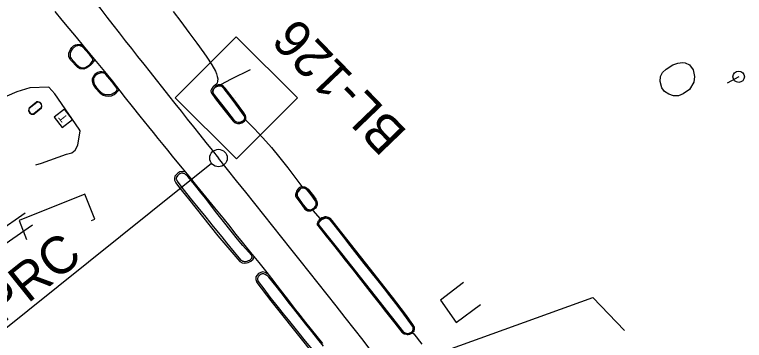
# Model space of a CAD drawing. Extents: x 471894 to 476235, y 503501 to 507878.
# Drawn here: x 473906 to 474218.9, y 505730.3 to 505870.1 of the extents above; entities that cross this region are included whole.
import ezdxf

# ---------------------------------------------------------------- set-up
doc = ezdxf.new("R2010")
doc.units = 0
for name, color, linetype in [('CTL Secondary Horizontal and Vertical CELL', 7, 'Continuous'), ('CTL Secondary Horizontal and Vertical Text', 7, 'Continuous'), ('Exist Horizontal Alignment', 7, 'Continuous'), ('Exist Other Culture Area Outline', 7, 'Continuous'), ('Exist Other Culture Sign', 7, 'Continuous'), ('Exist Roads Change in Surface', 7, 'Continuous'), ('Exist Roads Curbs', 7, 'Continuous'), ('Exist Roads EOP', 7, 'Continuous'), ('Exist Roads EOP Leader', 7, 'Continuous'), ('Exist Roads EOP Other', 7, 'Continuous'), ('Exist Roads Soil', 7, 'Continuous'), ('Exist Utilities Power Pole CELL', 7, 'Continuous'), ('Exist Utilities Telephone Pedestal CELL', 7, 'Continuous'), ('Exist Utilities Water Meter CELL', 7, 'Continuous')]:
    doc.layers.add(name, color=color, linetype=linetype)

msp = doc.modelspace()

# ---------------------------------------------------------------- linework, layer by layer
at = {"layer": 'CTL Secondary Horizontal and Vertical CELL'}
msp.add_line((474000.94, 505834.35), (474000.94, 505834.35), dxfattribs=at)
msp.add_lwpolyline([(473974.86, 505834.44), (474001.07, 505860.65), (474027.32, 505834.4), (474001.11, 505808.19)], close=True, dxfattribs=at)
at = {"layer": 'Exist Horizontal Alignment'}
msp.add_line((473990.5, 505806.21), (473896.83, 505731.16), dxfattribs=at)
msp.add_circle((473993.43, 505808.56), 3.75, dxfattribs=at)
for centre, radius, start, end in [((478558.54, 509466.62), 5849.93, 217.36226, 218.70549), ((466857.69, 500090.63), 9144.05, 37.455153, 38.70549)]:
    msp.add_arc(centre, radius, start, end, dxfattribs=at)
at = {"layer": 'Exist Other Culture Area Outline'}
msp.add_lwpolyline([(473938.96, 505781.69), (473940.43, 505782.28), (473936.12, 505793.05), (473907.96, 505781.79), (473911.21, 505773.67)], dxfattribs=at)
at = {"layer": 'Exist Other Culture Sign'}
for p, q in [((473910.56, 505784.93), (473869.89, 505756.79)), ((473873.24, 505752.05), (473913.74, 505779.89))]:
    msp.add_line(p, q, dxfattribs=at)
at = {"layer": 'Exist Roads Change in Surface'}
msp.add_lwpolyline([(474098.46, 505755.17), (474088.65, 505747.59), (474095.3, 505738.05), (474105.73, 505745.73)], dxfattribs=at)
at = {"layer": 'Exist Roads Curbs'}
for points in [[(473937.89, 505853.33), (473935.48, 505856.06), (473935.27, 505856.22), (473934.88, 505856.44), (473934.4, 505856.66), (473934.13, 505856.76), (473933.85, 505856.82), (473933.56, 505856.85), (473933.25, 505856.84), (473932.94, 505856.8), (473932.63, 505856.71), (473932.3, 505856.59), (473931.98, 505856.43), (473931.66, 505856.23), (473931.38, 505856.01), (473931.12, 505855.77), (473930.89, 505855.5), (473930.49, 505854.9), (473930.15, 505854.21), (473930.01, 505853.85), (473929.91, 505853.5), (473929.84, 505853.17), (473929.8, 505852.84), (473929.8, 505852.53), (473929.84, 505852.23), (473929.91, 505851.95), (473930.02, 505851.68), (473930.23, 505851.34), (473932.57, 505848.77), (473933.57, 505847.84), (473933.86, 505847.64), (473934.1, 505847.54), (473934.37, 505847.45), (473935.04, 505847.32), (473935.4, 505847.29), (473935.74, 505847.3), (473936.05, 505847.35), (473936.34, 505847.44), (473936.63, 505847.57), (473937.26, 505847.96), (473937.94, 505848.48), (473938.54, 505849.02), (473939.03, 505849.55), (473939.35, 505849.96), (473939.44, 505850.13), (473939.5, 505850.27), (473939.54, 505850.42), (473939.57, 505850.57), (473939.58, 505850.73), (473939.57, 505850.89), (473939.53, 505851.05), (473939.48, 505851.22), (473939.41, 505851.39), (473939.31, 505851.57), (473938.09, 505853.07)], [(473939.84, 505842.09), (473939.87, 505841.61), (473939.95, 505841.13), (473940.01, 505840.88), (473940.18, 505840.38), (473940.43, 505839.88), (473940.68, 505839.45), (473940.98, 505839.04), (473942.56, 505837.33), (473943.34, 505836.6), (473943.66, 505836.36), (473943.95, 505836.18), (473944.27, 505836.03), (473944.62, 505835.93), (473944.98, 505835.85), (473945.74, 505835.78), (473946.51, 505835.79), (473946.88, 505835.83), (473947.22, 505835.89), (473947.54, 505835.98), (473947.82, 505836.09), (473948.35, 505836.37), (473948.88, 505836.7), (473949.34, 505837.05), (473949.68, 505837.36), (473949.82, 505837.51), (473949.92, 505837.66), (473949.99, 505837.81), (473950.02, 505837.96), (473950.03, 505838.11), (473950.01, 505838.27), (473949.96, 505838.43), (473949.88, 505838.59), (473947.69, 505841.42), (473945.21, 505844.36), (473944.92, 505844.65), (473944.7, 505844.82), (473944.47, 505844.95), (473944.23, 505845.04), (473944, 505845.09), (473943.73, 505845.11), (473943.43, 505845.1), (473942.69, 505844.97), (473942.29, 505844.87), (473941.92, 505844.73), (473941.58, 505844.58), (473941.27, 505844.39), (473940.76, 505844.02), (473940.58, 505843.83), (473940.43, 505843.66), (473940.2, 505843.3), (473940, 505842.93), (473939.93, 505842.74), (473939.87, 505842.54), (473939.84, 505842.32)], [(473995.9, 505838.33), (473995.21, 505838.99), (473994.75, 505839.39), (473994.21, 505839.65), (473993.68, 505839.7), (473993.09, 505839.65), (473992.74, 505839.53), (473992.39, 505839.37), (473992.2, 505839.25), (473992.01, 505839.1), (473991.84, 505838.93), (473991.68, 505838.74), (473991.53, 505838.54), (473991.4, 505838.33), (473991.3, 505838.11), (473991.14, 505837.67), (473991.06, 505837.29), (473991.05, 505837.13), (473991.05, 505836.97), (473991.06, 505836.82), (473991.09, 505836.66), (473991.14, 505836.5), (473991.2, 505836.33), (473991.28, 505836.17), (473991.48, 505835.84), (473991.98, 505835.17), (473995.26, 505830.88), (473997.7, 505827.7), (473999.61, 505825.33), (474000.07, 505824.84), (474000.42, 505824.53), (474000.73, 505824.3), (474000.9, 505824.21), (474001.14, 505824.13), (474001.8, 505824), (474002.47, 505823.94), (474002.73, 505823.95), (474002.93, 505823.99), (474003.29, 505824.12), (474003.67, 505824.31), (474004.02, 505824.53), (474004.17, 505824.66), (474004.31, 505824.78), (474004.42, 505824.91), (474004.52, 505825.05), (474004.6, 505825.2), (474004.65, 505825.36), (474004.7, 505825.52), (474004.72, 505825.67), (474004.73, 505825.81), (474004.72, 505825.94), (474004.68, 505826.18), (474004.61, 505826.41), (474004.47, 505826.7), (474004.23, 505827.14), (474002.81, 505829.16), (474000.89, 505831.75), (473998.9, 505834.41)], [(473975.5, 505800.44), (473975.44, 505800.32), (473975.39, 505800.19), (473975.35, 505800.05), (473975.33, 505799.9), (473975.32, 505799.63), (473975.33, 505799.52), (473975.35, 505799.44), (473975.39, 505799.32), (473975.74, 505798.59), (473976, 505798.16), (473978.78, 505794.58), (473981.35, 505791.39), (473984.64, 505787.29), (473987.95, 505783.21), (473991.21, 505779.2), (473994.87, 505774.7), (473996.87, 505772.24), (474000.19, 505768.16), (474003.08, 505764.79), (474003.22, 505764.69), (474003.4, 505764.58), (474003.91, 505764.35), (474004.21, 505764.25), (474004.51, 505764.19), (474004.81, 505764.17), (474005.1, 505764.2), (474005.69, 505764.33), (474006.29, 505764.54), (474006.83, 505764.8), (474007.05, 505764.93), (474007.23, 505765.07), (474007.38, 505765.21), (474007.51, 505765.36), (474007.63, 505765.51), (474007.72, 505765.66), (474007.78, 505765.82), (474007.83, 505765.97), (474007.85, 505766.13), (474007.84, 505766.3), (474007.79, 505766.47), (474007.7, 505766.67), (474007.55, 505766.9), (474003.93, 505771.02), (474001.65, 505773.73), (473998.82, 505777.23), (473995.57, 505781.32), (473992.72, 505784.96), (473990.42, 505787.92), (473987.83, 505791.31), (473985.9, 505793.77), (473983.11, 505797.28), (473980.49, 505800.48), (473979.95, 505801.04), (473979.49, 505801.43), (473979.02, 505801.72), (473978.56, 505801.93), (473978.36, 505802), (473978.19, 505802.05), (473978.03, 505802.08), (473977.89, 505802.09), (473977.76, 505802.08), (473977.62, 505802.07), (473977.5, 505802.04), (473976.9, 505801.81), (473976.73, 505801.73), (473976.57, 505801.63), (473976.41, 505801.51), (473976.11, 505801.25), (473975.87, 505801), (473975.57, 505800.56)], [(474033.16, 505792.74), (474031.27, 505795.02), (474031.04, 505795.23), (474030.8, 505795.41), (474030.66, 505795.49), (474030.49, 505795.56), (474030.29, 505795.62), (474030.05, 505795.67), (474029.8, 505795.71), (474029.57, 505795.72), (474029.34, 505795.7), (474029.12, 505795.66), (474028.91, 505795.6), (474028.71, 505795.51), (474028.51, 505795.4), (474028.12, 505795.11), (474027.8, 505794.83), (474027.68, 505794.69), (474027.56, 505794.54), (474027.45, 505794.37), (474027.25, 505793.97), (474027.09, 505793.57), (474026.99, 505793.24), (474026.97, 505793.09), (474026.96, 505792.93), (474026.97, 505792.78), (474027, 505792.62), (474027.05, 505792.43), (474027.16, 505792.2), (474030.21, 505787.79), (474030.77, 505787.08), (474031.08, 505786.76), (474031.38, 505786.52), (474031.54, 505786.43), (474031.72, 505786.35), (474031.92, 505786.29), (474032.15, 505786.25), (474032.38, 505786.23), (474032.59, 505786.23), (474032.77, 505786.24), (474032.93, 505786.28), (474033.22, 505786.39), (474033.49, 505786.52), (474033.8, 505786.72), (474034.57, 505787.36), (474034.71, 505787.5), (474035.07, 505787.98), (474035.21, 505788.21), (474035.26, 505788.32), (474035.31, 505788.43), (474035.33, 505788.55), (474035.37, 505788.78), (474035.38, 505789.02), (474035.37, 505789.25), (474035.35, 505789.36), (474035.3, 505789.57), (474035.08, 505790.1), (474034.96, 505790.33)], [(474060.68, 505748.99), (474062.78, 505746.3), (474066.4, 505741.66), (474069.18, 505738.08), (474071.8, 505734.77), (474072.61, 505733.9), (474072.83, 505733.72), (474073.04, 505733.58), (474073.25, 505733.48), (474073.46, 505733.41), (474073.91, 505733.33), (474074.39, 505733.28), (474074.65, 505733.28), (474074.91, 505733.31), (474075.18, 505733.38), (474075.46, 505733.49), (474075.95, 505733.74), (474076.15, 505733.87), (474076.32, 505734.01), (474076.47, 505734.15), (474076.6, 505734.3), (474076.71, 505734.47), (474076.81, 505734.65), (474076.88, 505734.83), (474076.93, 505735.03), (474076.96, 505735.23), (474076.96, 505735.43), (474076.93, 505735.65), (474076.87, 505735.87), (474076.78, 505736.11), (474076.66, 505736.37), (474074.8, 505739.04), (474072.92, 505741.57), (474070.44, 505744.84), (474066.91, 505749.42), (474064.57, 505752.4), (474061.85, 505755.85), (474058.92, 505759.57), (474055.95, 505763.35), (474052.94, 505767.19), (474049.9, 505771.08), (474047.15, 505774.6), (474043.59, 505779.16), (474041.29, 505781.98), (474041.12, 505782.14), (474040.95, 505782.27), (474040.78, 505782.38), (474040.59, 505782.48), (474040.41, 505782.56), (474040.21, 505782.63), (474039.8, 505782.73), (474039.4, 505782.78), (474039, 505782.8), (474038.8, 505782.78), (474038.6, 505782.75), (474038.21, 505782.65), (474038.05, 505782.59), (474037.92, 505782.53), (474037.83, 505782.47), (474037.33, 505782.08), (474037.02, 505781.81), (474036.9, 505781.66), (474036.7, 505781.38), (474036.54, 505781.08), (474036.41, 505780.79), (474036.37, 505780.66), (474036.35, 505780.54), (474036.34, 505780.44), (474036.34, 505780.26), (474036.36, 505780.09), (474036.4, 505779.93), (474036.46, 505779.76), (474036.49, 505779.67), (474036.54, 505779.59), (474036.6, 505779.5), (474037.55, 505778.36), (474041.24, 505773.77), (474044.11, 505770.12), (474047.87, 505765.34), (474051.82, 505760.3), (474055.27, 505755.9), (474058.22, 505752.13)]]:
    msp.add_lwpolyline(points, close=True, dxfattribs=at)
for points in [[(473991.07, 505836.47), (473996.93, 505828.95), (474000.21, 505824.62), (474001.16, 505824.07), (474002.01, 505823.9), (474003.04, 505824.09), (474003.83, 505824.48), (474004.57, 505824.99), (474004.86, 505825.56), (474004.92, 505826.1), (474004.81, 505826.68), (474004.56, 505827.08), (473997.32, 505836.66), (473995.69, 505838.64), (473994.63, 505839.38), (473994.25, 505839.44), (473993.42, 505839.42), (473992.55, 505839.13), (473992.01, 505838.8), (473991.31, 505838.16), (473991.03, 505837.64), (473990.84, 505837.22), (473991.07, 505836.47)], [(474027.18, 505792.03), (474029.19, 505789.26), (474031.24, 505786.81), (474032.88, 505786.31), (474033.71, 505786.63), (474034.64, 505787.26), (474035.13, 505788.05), (474035.48, 505788.9), (474035.47, 505789.63), (474035.16, 505790.37), (474031.51, 505795.16), (474030.11, 505795.66), (474028.95, 505795.58), (474028.25, 505795.04), (474027.51, 505794.1), (474027.2, 505793.57), (474027.18, 505792.03)], [(474038.48, 505727.77), (474035.98, 505730.89), (474033.41, 505734.1), (474030.85, 505737.33), (474028.29, 505740.57), (474025.75, 505743.84), (474023.37, 505746.9), (474021.3, 505749.56), (474018.13, 505753.64), (474015.06, 505757.46), (474014.79, 505757.72), (474014.5, 505757.97), (474014.18, 505758.2), (474013.5, 505758.59), (474013.19, 505758.72), (474012.91, 505758.81), (474012.67, 505758.86), (474012.44, 505758.86), (474012.2, 505758.83), (474011.95, 505758.77), (474011.7, 505758.67), (474011.45, 505758.54), (474011.22, 505758.39), (474010.99, 505758.21), (474010.78, 505758), (474010.6, 505757.78), (474010.45, 505757.56), (474010.34, 505757.33), (474010.27, 505757.1), (474010.23, 505756.87), (474010.2, 505756.66), (474010.2, 505756.46), (474010.22, 505756.29), (474010.26, 505756.12), (474010.31, 505755.95), (474010.38, 505755.78), (474010.46, 505755.61), (474012.85, 505752.36), (474015.51, 505748.92), (474019.1, 505744.36), (474021.17, 505741.76), (474023.33, 505739.07), (474025.57, 505736.29), (474027.9, 505733.41), (474030.1, 505730.71), (474033.4, 505726.59)]]:
    msp.add_lwpolyline(points, dxfattribs=at)
at = {"layer": 'Exist Roads EOP'}
for points in [[(474038.16, 505728.97), (474035.74, 505731.99), (474033.34, 505735.01), (474030.94, 505738.02), (474028.52, 505741.06), (474026.06, 505744.19), (474023.56, 505747.41), (474021.01, 505750.71), (474018.55, 505753.9), (474016.31, 505756.8), (474014.29, 505759.39), (474010.9, 505763.69), (474007.36, 505768.01), (474004.88, 505771.01), (474003.1, 505773.23), (474000.95, 505775.94), (473998.39, 505779.15), (473995.39, 505782.88), (473991.93, 505787.14), (473988.03, 505791.93), (473984.17, 505796.65), (473980.84, 505800.73), (473978.04, 505804.16), (473975.77, 505806.94), (473973.76, 505809.41), (473971.74, 505811.9), (473969.69, 505814.43), (473967.63, 505816.97), (473965.6, 505819.49), (473963.63, 505821.92), (473959.9, 505826.53), (473956.52, 505830.73), (473953.59, 505834.48), (473951.29, 505837.48), (473948, 505841.7), (473944.74, 505845.65), (473941.12, 505850), (473938.25, 505853.47), (473935.57, 505856.72), (473932.54, 505860.4), (473929.43, 505864.18), (473926.5, 505867.73), (473923.38, 505871.52)], [(473973.95, 505871.54), (473977.33, 505867.11), (473980.77, 505862.51), (473984.14, 505857.93), (473987.18, 505853.7), (473988.48, 505851.84), (473990.63, 505848.59), (473992.12, 505845.86), (473992.62, 505844.68), (473992.95, 505843.59), (473993.1, 505842.57), (473993.08, 505841.61), (473992.89, 505840.71), (473992.23, 505840.01), (473991.21, 505839.13), (473991.02, 505838.94), (473990.7, 505838.53), (473990.47, 505838.19), (473990.31, 505837.89), (473990.23, 505837.6), (473990.2, 505837.3), (473990.25, 505836.99), (473990.37, 505836.66), (473990.59, 505836.25), (473992.22, 505833.99), (473994.21, 505831.39), (473996.28, 505828.72), (473999.78, 505824.37), (474000.22, 505823.98), (474000.38, 505823.86), (474000.55, 505823.76), (474000.74, 505823.68), (474001.18, 505823.54), (474001.63, 505823.45), (474001.85, 505823.42), (474002.07, 505823.41), (474002.31, 505823.42), (474002.55, 505823.45), (474003.04, 505823.57), (474003.27, 505823.64), (474003.47, 505823.73), (474004.18, 505824.15), (474004.53, 505824.4), (474004.89, 505824.76), (474005.08, 505824.97), (474008.81, 505821.23), (474012.5, 505817.25), (474016.17, 505813.05), (474019.81, 505808.61), (474023.11, 505804.43), (474025.78, 505800.99), (474029.12, 505796.29), (474028.59, 505796.1), (474028.42, 505796.02), (474028.25, 505795.92), (474027.92, 505795.66), (474027.62, 505795.38), (474027.37, 505795.09), (474027.13, 505794.73), (474026.89, 505794.3), (474026.7, 505793.84), (474026.55, 505793.37), (474026.46, 505792.91), (474026.44, 505792.5), (474026.46, 505792.21), (474026.62, 505791.89), (474029.15, 505788.42), (474030.52, 505786.69), (474030.87, 505786.37), (474031.04, 505786.25), (474031.35, 505786.09), (474031.66, 505785.97), (474031.98, 505785.9), (474032.31, 505785.86), (474032.64, 505785.86), (474032.99, 505785.92), (474033.34, 505786.02), (474033.61, 505786.14), (474033.87, 505786.01), (474037, 505782.43), (474036.46, 505781.86), (474036.29, 505781.65), (474036.1, 505781.33), (474035.97, 505781.03), (474035.85, 505780.72), (474035.79, 505780.42), (474035.78, 505780.15), (474035.81, 505779.93), (474036.02, 505779.58), (474039.62, 505775.05), (474042.2, 505771.82), (474044.9, 505768.43), (474047.76, 505764.78), (474050.84, 505760.84), (474054.34, 505756.37), (474056.27, 505753.91), (474058.31, 505751.32), (474060.46, 505748.57), (474062.73, 505745.69), (474065.1, 505742.66), (474067.31, 505739.86), (474069.05, 505737.65), (474072.11, 505733.86), (474072.45, 505733.53), (474072.67, 505733.35), (474073.02, 505733.18), (474073.35, 505733.06), (474074.02, 505732.92), (474074.37, 505732.88), (474074.72, 505732.89), (474075.08, 505732.93), (474075.44, 505733.03), (474076.56, 505733.52), (474077.22, 505733.16), (474080.64, 505728.7)]]:
    msp.add_lwpolyline(points, dxfattribs=at)
at = {"layer": 'Exist Roads EOP Leader'}
msp.add_lwpolyline([(474072.77, 505719.35), (474153.88, 505748.66), (474167.52, 505734.48)], dxfattribs=at)
at = {"layer": 'Exist Roads EOP Other'}
for points in [[(473992.47, 505839.86), (473993.44, 505840.11), (473994.39, 505840.2), (473999.07, 505842.61), (474007.13, 505846.51)], [(473915.15, 505805.66), (473917.63, 505806.4), (473928.31, 505810.2), (473930.53, 505810.78), (473931.98, 505811.98), (473933.15, 505814.1), (473934.08, 505820.3), (473933.68, 505820.95), (473923.27, 505836.19), (473920.73, 505838.99), (473912.59, 505838.72), (473906.98, 505836.93), (473894.99, 505831.87), (473900.48, 505817.81), (473899.87, 505817.2)]]:
    msp.add_lwpolyline(points, dxfattribs=at)
at = {"layer": 'Exist Roads Soil'}
for points in [[(473940.11, 505850.93), (473940.08, 505850.49), (473939.9, 505849.98), (473939.53, 505849.39), (473938.79, 505848.63), (473937.83, 505847.83), (473937.03, 505847.25), (473935.72, 505846.72), (473934.14, 505846.93), (473933.13, 505847.45), (473929.85, 505850.87), (473929.26, 505852.1), (473929.34, 505853.59), (473930, 505855.14), (473930.53, 505855.99), (473931.34, 505856.71), (473932.08, 505857.13), (473932.85, 505857.34), (473933.61, 505857.37), (473934.37, 505857.29), (473935.1, 505856.91), (473935.43, 505856.69)], [(474195.32, 505848.52), (474196.88, 505846.49), (474197.55, 505843.51), (474197.26, 505841.12), (474195.44, 505838.02), (474192.61, 505836.07), (474190.66, 505835.25), (474188.55, 505835.32), (474186.52, 505835.98), (474184.72, 505837.13), (474183.48, 505838.67), (474182.77, 505841.48), (474183.01, 505843.55), (474183.77, 505845.25), (474185.33, 505846.71), (474188.24, 505848.51), (474190.33, 505849.36), (474192.32, 505849.56), (474193.49, 505849.41), (474195.32, 505848.52)], [(473944.96, 505845.18), (473944.29, 505845.43), (473943.41, 505845.56), (473942.61, 505845.53), (473941.73, 505845.27), (473940.95, 505844.83), (473940.42, 505844.41), (473939.84, 505843.72), (473939.54, 505843.21), (473939.32, 505842.55), (473939.35, 505841.56), (473939.57, 505840.48), (473940.12, 505839.36), (473940.68, 505838.59), (473942.76, 505836.37), (473943.94, 505835.55), (473945.07, 505835.29), (473946.46, 505835.13), (473947.52, 505835.22), (473948.73, 505835.82), (473949.65, 505836.52), (473950.62, 505837.61), (473950.8, 505838.01)], [(474005.09, 505825.01), (474005.19, 505825.4), (474005.2, 505825.79), (474005.16, 505826.23), (474005, 505826.82), (474004.36, 505827.93), (474000.27, 505833.43), (473996.36, 505838.62), (473995.64, 505839.32), (473994.56, 505840.06)], [(473979.45, 505802.33), (473978.96, 505802.59), (473978.07, 505802.82), (473976.93, 505802.62), (473976.01, 505802.13), (473975.24, 505801.4), (473974.78, 505800.77), (473974.53, 505799.94), (473974.62, 505799.14), (473975.2, 505797.92), (473976.79, 505795.84), (473980.63, 505791.1), (473993.12, 505775.21), (474002.64, 505764.12), (474003.56, 505763.65), (474004.69, 505763.4), (474006.17, 505763.72), (474007.27, 505764.28), (474008.26, 505765.15), (474008.61, 505766.02)], [(474029.25, 505796.27), (474029.67, 505796.23), (474030.25, 505796.14), (474030.75, 505796.02), (474031.32, 505795.66), (474031.85, 505795.17), (474034.17, 505792.3), (474035.21, 505790.87), (474035.45, 505790.38), (474035.8, 505789.3), (474035.74, 505788.29), (474035.43, 505787.7), (474035, 505787.11), (474034.26, 505786.52), (474033.82, 505786.26)], [(474036.43, 505779.79), (474046.15, 505767.6), (474060.56, 505749.25), (474072.73, 505733.88), (474074.69, 505733.08), (474075.82, 505733.39), (474076.47, 505733.85), (474076.92, 505734.47), (474077.11, 505735.51), (474077.03, 505736.2), (474076.59, 505737.3), (474064.41, 505752.91), (474048.09, 505774.09), (474041.03, 505782.4), (474039.43, 505782.78), (474038.55, 505782.53), (474037.64, 505782.11), (474037.04, 505781.49), (474036.49, 505780.96), (474036.37, 505780.59), (474036.43, 505779.79)], [(474037.05, 505782.48), (474037.14, 505782.56), (474037.8, 505783.07), (474038.32, 505783.24), (474038.83, 505783.32)], [(474077.48, 505735.05), (474077.42, 505735.98), (474076.81, 505737.15), (474073.61, 505741.5), (474068.07, 505748.79), (474056.41, 505763.53), (474044.17, 505779.25), (474042.15, 505781.77), (474041.45, 505782.57), (474040.61, 505783.06), (474039.66, 505783.27), (474038.83, 505783.32)], [(474014.51, 505758.85), (474013.4, 505759.5), (474012.35, 505759.68), (474010.66, 505759.03), (474010.01, 505758.31), (474009.52, 505757.51), (474009.44, 505756.42), (474009.86, 505755.18), (474015.85, 505747.27), (474030.57, 505728.76), (474039.3, 505717.6), (474043.29, 505712.6), (474044.37, 505711.65), (474045.72, 505710.99), (474047.14, 505710.82)], [(474076.92, 505733.9), (474077.27, 505734.28), (474077.48, 505735.05)]]:
    msp.add_lwpolyline(points, dxfattribs=at)
at = {"layer": 'Exist Utilities Power Pole CELL'}
for q in [(474211.55, 505840.74), (474216.46, 505843.48)]:
    msp.add_line((474216.46, 505843.48), q, dxfattribs=at)
msp.add_circle((474216.46, 505843.48), 2.45, dxfattribs=at)
at = {"layer": 'Exist Utilities Telephone Pedestal CELL'}
msp.add_line((473926.99, 505825.55), (473926.99, 505825.55), dxfattribs=at)
msp.add_lwpolyline([(473930.9, 505825.14), (473927.46, 505829.56), (473923.04, 505826.12), (473926.48, 505821.7), (473930.9, 505825.14)], dxfattribs=at)
at = {"layer": 'Exist Utilities Water Meter CELL'}
msp.add_line((473914.92, 505830.03), (473914.92, 505830.03), dxfattribs=at)
for points in [[(473912.26, 505830.07), (473915.43, 505832.63)], [(473912.35, 505829.96), (473915.52, 505832.52)], [(473917.48, 505830.09), (473914.3, 505827.51)], [(473917.57, 505829.99), (473914.38, 505827.41)]]:
    msp.add_lwpolyline(points, dxfattribs=at)
for centre, radius, start, end in [((473915.92, 505830.84), 1.86, 332.6482, 105.3083), ((473915.93, 505830.85), 1.73, 334.1271, 103.8728), ((473913.9, 505829.2), 1.86, 152.178, 284.9793), ((473913.91, 505829.21), 1.73, 154.3009, 282.7823)]:
    msp.add_arc(centre, radius, start, end, dxfattribs=at)

# ---------------------------------------------------------------- texts
at = {"layer": 'CTL Secondary Horizontal and Vertical Text'}
msp.add_text('BL-126', height=16, rotation=133.8986, dxfattribs=at).set_placement((474074.86, 505819.7))
at = {"layer": 'Exist Horizontal Alignment'}
msp.add_text('PRC', height=16, rotation=38.7055, dxfattribs=at).set_placement((473900.57, 505737))
at = {"layer": 'Exist Utilities Telephone Pedestal CELL'}
msp.add_text('T', height=3.42, rotation=127.9234, dxfattribs=at).set_placement((473929.04, 505825.72))

doc.saveas('drawing.dxf')
